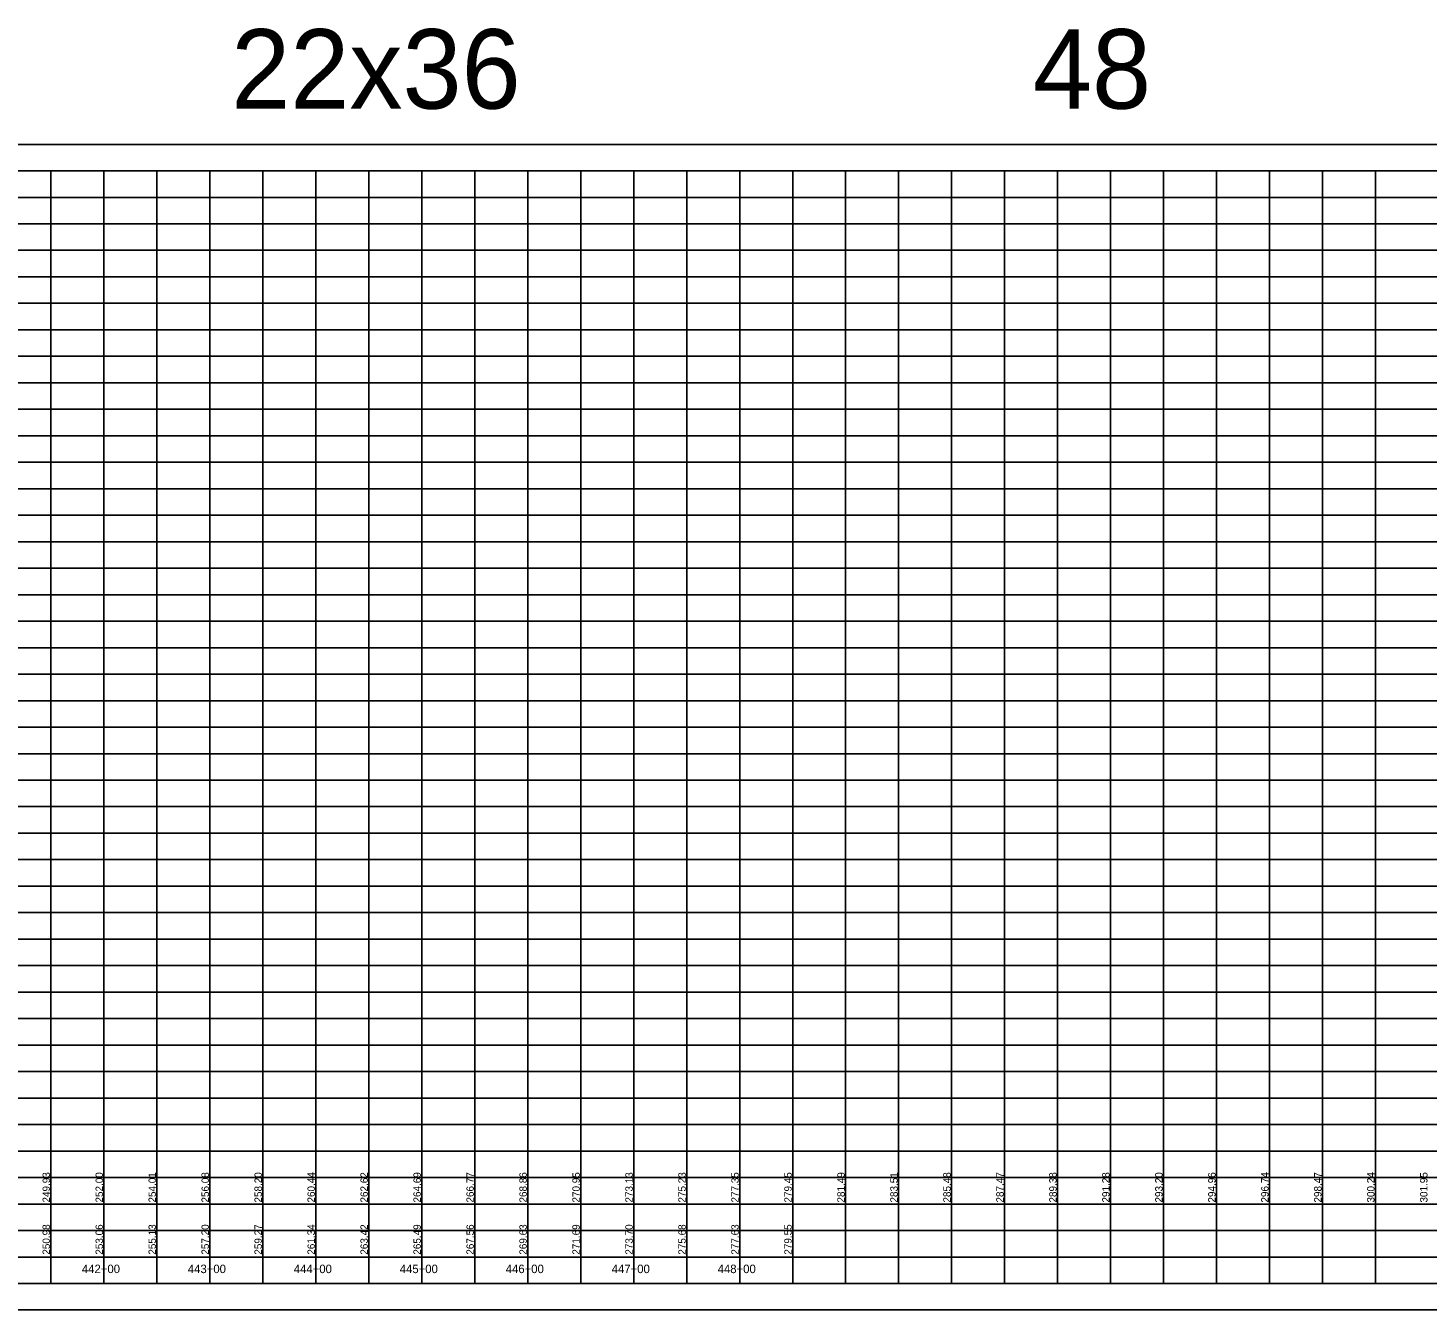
# Model space of a CAD drawing. Extents: x 1873632 to 1926512, y 813126 to 836257.
# Drawn here: x 1922491 to 1923813, y 828238 to 829448 of the extents above; entities that cross this region are included whole.
import ezdxf

# ---------------------------------------------------------------- set-up
doc = ezdxf.new("R2010")
doc.units = 0
for name, color, linetype in [('RD_DDB_StaTX', 7, 'Continuous'), ('RD_DDB_StripGrade', 7, 'Continuous'), ('RD_PD_WallFill', 7, 'Continuous'), ('RD_SHT_IplotShp', 7, 'Continuous')]:
    doc.layers.add(name, color=color, linetype=linetype)

msp = doc.modelspace()

# ---------------------------------------------------------------- linework, layer by layer
at = {"layer": 'RD_PD_WallFill'}
for p, q in [((1921113, 829313.1), (1926463, 829313.1)), ((1921113, 829313.1), (1922863, 829313.1)), ((1922513, 828263.1), (1922513, 829313.1)), ((1922513, 828263.1), (1922513, 829313.1)), ((1922563, 828263.1), (1922563, 829313.1)), ((1922563, 828263.1), (1922563, 829313.1)), ((1922613, 828263.1), (1922613, 829313.1)), ((1922613, 828263.1), (1922613, 829313.1)), ((1922663, 828263.1), (1922663, 829313.1)), ((1922663, 828263.1), (1922663, 829313.1)), ((1922713, 828263.1), (1922713, 829313.1)), ((1922713, 828263.1), (1922713, 829313.1)), ((1922763, 828263.1), (1922763, 829313.1)), ((1922763, 828263.1), (1922763, 829313.1)), ((1922813, 828263.1), (1922813, 829313.1)), ((1922813, 828263.1), (1922813, 829313.1)), ((1922863, 828263.1), (1922863, 829313.1)), ((1922863, 828263.1), (1922863, 829313.1)), ((1922913, 828263.1), (1922913, 829313.1)), ((1922913, 828263.1), (1922913, 829313.1)), ((1922963, 828263.1), (1922963, 829313.1)), ((1922963, 828263.1), (1922963, 829313.1)), ((1923013, 828263.1), (1923013, 829313.1)), ((1923013, 828263.1), (1923013, 829313.1)), ((1923063, 828263.1), (1923063, 829313.1)), ((1923063, 828263.1), (1923063, 829313.1)), ((1923113, 828263.1), (1923113, 829313.1)), ((1923113, 828263.1), (1923113, 829313.1)), ((1923163, 828263.1), (1923163, 829313.1)), ((1923163, 828263.1), (1923163, 829313.1)), ((1923213, 828263.1), (1923213, 829313.1)), ((1923213, 828263.1), (1923213, 829313.1)), ((1923263, 828263.1), (1923263, 829313.1)), ((1923263, 828263.1), (1923263, 829313.1)), ((1923313, 828263.1), (1923313, 829313.1)), ((1923313, 828263.1), (1923313, 829313.1)), ((1923363, 828263.1), (1923363, 829313.1)), ((1923363, 828263.1), (1923363, 829313.1)), ((1923413, 828263.1), (1923413, 829313.1)), ((1923413, 828263.1), (1923413, 829313.1)), ((1923463, 828263.1), (1923463, 829313.1)), ((1923463, 828263.1), (1923463, 829313.1)), ((1923513, 828263.1), (1923513, 829313.1)), ((1923513, 828263.1), (1923513, 829313.1)), ((1923563, 828263.1), (1923563, 829313.1)), ((1923563, 828263.1), (1923563, 829313.1)), ((1923613, 828263.1), (1923613, 829313.1)), ((1923613, 828263.1), (1923613, 829313.1)), ((1923663, 828263.1), (1923663, 829313.1)), ((1923663, 828263.1), (1923663, 829313.1)), ((1923713, 828263.1), (1923713, 829313.1)), ((1923713, 828263.1), (1923713, 829313.1)), ((1923763, 828263.1), (1923763, 829313.1)), ((1923763, 828263.1), (1923763, 829313.1)), ((1921563, 829288.1), (1926463, 829288.1)), ((1921563, 829288.1), (1926463, 829288.1)), ((1921563, 829263.1), (1926463, 829263.1)), ((1921563, 829238.1), (1926463, 829238.1)), ((1921563, 829213.1), (1926463, 829213.1)), ((1921563, 829188.1), (1926463, 829188.1)), ((1921113, 829163.1), (1926463, 829163.1)), ((1921113, 829138.1), (1926463, 829138.1)), ((1921113, 829113.1), (1926463, 829113.1)), ((1921113, 829088.1), (1926463, 829088.1)), ((1921113, 829063.1), (1926463, 829063.1)), ((1921113, 829038.1), (1926463, 829038.1)), ((1921113, 829013.1), (1926463, 829013.1)), ((1921113, 828988.1), (1926463, 828988.1)), ((1921113, 828963.1), (1926463, 828963.1)), ((1921113, 828938.1), (1926463, 828938.1)), ((1921113, 828913.1), (1926463, 828913.1)), ((1921113, 828888.1), (1926463, 828888.1)), ((1921113, 828863.1), (1926463, 828863.1)), ((1921113, 828838.1), (1926463, 828838.1)), ((1921113, 828813.1), (1926463, 828813.1)), ((1921113, 828788.1), (1926463, 828788.1)), ((1921113, 828763.1), (1926463, 828763.1)), ((1921113, 828738.1), (1926463, 828738.1)), ((1921113, 828713.1), (1926463, 828713.1)), ((1921113, 828688.1), (1926463, 828688.1)), ((1921113, 828663.1), (1926463, 828663.1)), ((1921113, 828638.1), (1926463, 828638.1)), ((1921113, 828613.1), (1926463, 828613.1)), ((1921113, 828588.1), (1926463, 828588.1)), ((1921113, 828563.1), (1926463, 828563.1)), ((1921113, 828538.1), (1926463, 828538.1)), ((1921113, 828513.1), (1926463, 828513.1)), ((1921113, 828488.1), (1926463, 828488.1)), ((1921113, 828463.1), (1926463, 828463.1)), ((1921113, 828438.1), (1926463, 828438.1)), ((1921113, 828413.1), (1926463, 828413.1)), ((1921113, 828388.1), (1926463, 828388.1)), ((1921113, 828363.1), (1926463, 828363.1)), ((1921113, 828338.1), (1926463, 828338.1)), ((1921113, 828313.1), (1926463, 828313.1)), ((1921113, 828288.1), (1926463, 828288.1)), ((1921113, 828263.1), (1926463, 828263.1)), ((1921113, 828263.1), (1926463, 828263.1))]:
    msp.add_line(p, q, dxfattribs=at)
at = {"layer": 'RD_SHT_IplotShp'}
msp.add_lwpolyline([(1921088, 828238.1), (1926488, 828238.1), (1926488, 829338.1), (1921088, 829338.1)], close=True, dxfattribs=at)

# ---------------------------------------------------------------- texts
at = {"layer": 'RD_DDB_StaTX'}
for s, p in [('442+00', (1922542.2, 828272.9)), ('443+00', (1922642.2, 828272.9)), ('444+00', (1922742.2, 828272.9)), ('445+00', (1922842.2, 828272.9)), ('446+00', (1922942.2, 828272.9)), ('447+00', (1923042.2, 828272.9)), ('448+00', (1923142.2, 828272.9))]:
    msp.add_text(s, height=8, dxfattribs=at).set_placement(p)
at = {"layer": 'RD_DDB_StripGrade'}
for s, p in [('249.93', (1922512.1, 828339.5)), ('252.00', (1922562.1, 828339.5)), ('254.01', (1922612.1, 828339.5)), ('256.08', (1922662.1, 828339.5)), ('258.20', (1922712.1, 828339.5)), ('260.44', (1922762.1, 828339.5)), ('262.62', (1922812.1, 828339.5)), ('264.69', (1922862.1, 828339.5)), ('266.77', (1922912.1, 828339.5)), ('268.86', (1922962.1, 828339.5)), ('270.95', (1923012.1, 828339.5)), ('273.13', (1923062.1, 828339.5)), ('275.23', (1923112.1, 828339.5)), ('277.35', (1923162.1, 828339.5)), ('279.45', (1923212.1, 828339.5)), ('281.49', (1923262.1, 828339.5)), ('283.51', (1923312.1, 828339.5)), ('285.48', (1923362.1, 828339.5)), ('287.47', (1923412.1, 828339.5)), ('289.38', (1923462.1, 828339.5)), ('291.28', (1923512.1, 828339.5)), ('293.20', (1923562.1, 828339.5)), ('294.96', (1923612.1, 828339.5)), ('296.74', (1923662.1, 828339.5)), ('298.47', (1923712.1, 828339.5)), ('300.24', (1923762.1, 828339.5)), ('301.95', (1923812.1, 828339.5)), ('250.98', (1922512.1, 828290.3)), ('253.06', (1922562.1, 828290.3)), ('255.13', (1922612.1, 828290.3)), ('257.20', (1922662.1, 828290.3)), ('259.27', (1922712.1, 828290.3)), ('261.34', (1922762.1, 828290.3)), ('263.42', (1922812.1, 828290.3)), ('265.49', (1922862.1, 828290.3)), ('267.56', (1922912.1, 828290.3)), ('269.63', (1922962.1, 828290.3)), ('271.69', (1923012.1, 828290.3)), ('273.70', (1923062.1, 828290.3)), ('275.68', (1923112.1, 828290.3)), ('277.63', (1923162.1, 828290.3)), ('279.55', (1923212.1, 828290.3))]:
    msp.add_text(s, height=7, rotation=90, dxfattribs=at).set_placement(p)
at = {"layer": 'RD_PD_WallFill'}
for s, p in [('22x36', (1922683.1, 829371.8)), ('22x36', (1922683.1, 829371.8)), ('48', (1923439.7, 829371.8)), ('48', (1923439.7, 829371.8))]:
    msp.add_text(s, height=75, dxfattribs=at).set_placement(p)

doc.saveas('drawing.dxf')
